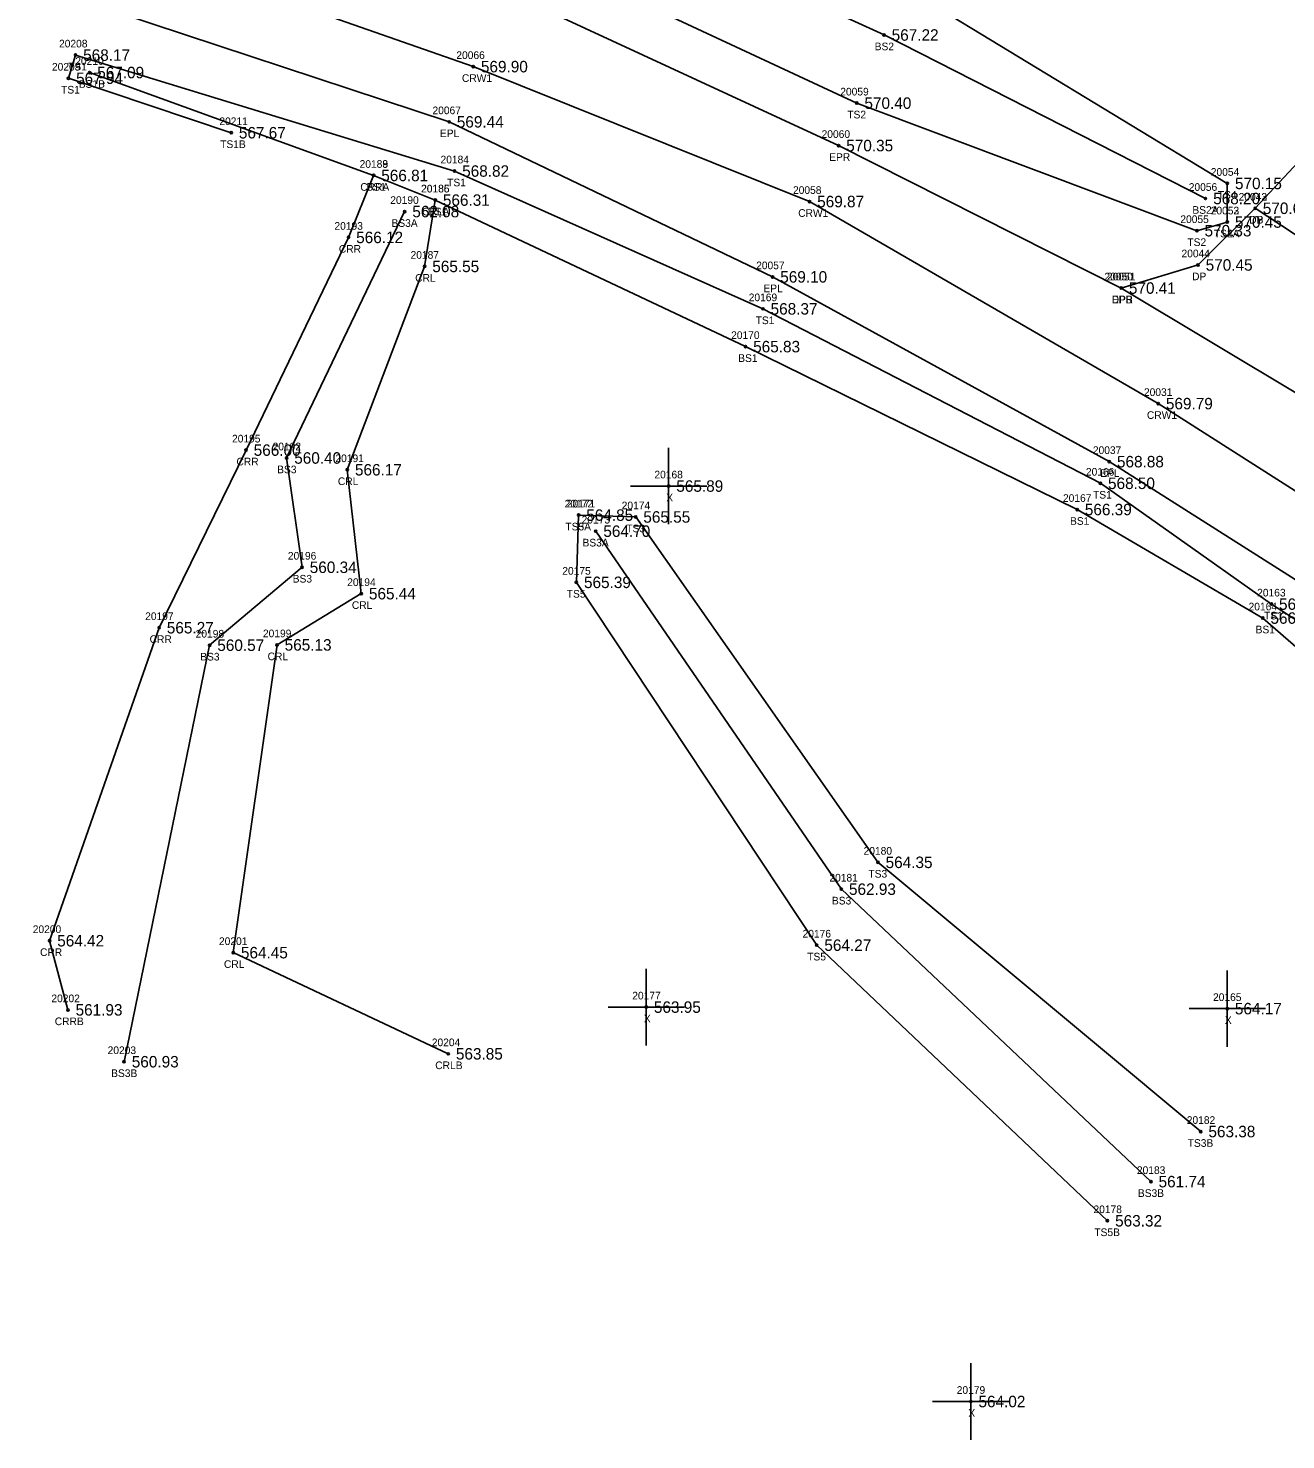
# Model space of a CAD drawing. Extents: x 1530159 to 1531652, y 877045 to 877724.
# Drawn here: x 1531368.6 to 1531533, y 877049.7 to 877234.2 of the extents above; entities that cross this region are included whole.
import ezdxf

# ---------------------------------------------------------------- set-up
doc = ezdxf.new("R2010")
doc.units = 0
for name, color, linetype in [('RD_DTM_BkLn1', 7, 'Continuous'), ('RD_DTM_BkLn2', 7, 'Continuous'), ('RD_DTM_BkLn_txCode', 7, 'Continuous'), ('RD_EX_Driveway', 7, 'Continuous'), ('RD_EX_Driveway_txCode', 7, 'Continuous'), ('RD_EX_H2O', 7, 'Continuous'), ('RD_EX_H2O_txCode', 7, 'Continuous'), ('RD_EX_Misc', 7, 'Continuous'), ('RD_EX_Misc_txCode', 7, 'Continuous'), ('RD_EX_Road', 7, 'Continuous'), ('RD_EX_Road_txCode', 7, 'Continuous'), ('RD_EX_TX_Driveway_ELEV', 7, 'Continuous'), ('RD_EX_TX_H2O_ELEV', 7, 'Continuous'), ('RD_EX_TX_Misc_ELEV', 7, 'Continuous'), ('RD_EX_TX_Road_ELEV', 7, 'Continuous'), ('RD_HC_Survey_ELEV', 7, 'Continuous'), ('RD_HC_Survey_txCode', 7, 'Continuous'), ('RD_SMD_Locator', 7, 'Continuous')]:
    doc.layers.add(name, color=color, linetype=linetype)

msp = doc.modelspace()

# ---------------------------------------------------------------- linework, layer by layer
at = {"layer": 'RD_DTM_BkLn1'}
msp.add_lwpolyline([(1531601.44, 877127.51), (1531558.79, 877158.11), (1531516.37, 877185.16), (1531470.77, 877211.58), (1531426.8, 877229.22), (1531379.86, 877245.66), (1531330.99, 877260.09), (1531284.24, 877270.97), (1531236.44, 877276.73), (1531185.96, 877281.19), (1531132.29, 877281.48), (1531081.11, 877280.78), (1531028.25, 877278.4), (1530978.85, 877276.13), (1530941.18, 877274.78)], dxfattribs=at)
at = {"layer": 'RD_DTM_BkLn2'}
for points in [[(1531525.39, 877208.9), (1531521.42, 877207.77), (1531476.95, 877224.45), (1531434.54, 877244.21), (1531428.71, 877250.7), (1531428.74, 877257.42), (1531435.09, 877260.65), (1531443.68, 877258)], [(1531525.39, 877208.9), (1531525.4, 877213.95), (1531484.44, 877238.83), (1531443.68, 877258)], [(1531522.55, 877211.98), (1531480.51, 877233.36), (1531446.11, 877249.05), (1531438.91, 877251.49), (1531432.85, 877253.78)], [(1531591.14, 877115.14), (1531551.46, 877145.84), (1531531.16, 877158.94), (1531508.8, 877174.74), (1531464.68, 877197.55), (1531424.35, 877215.57), (1531374.79, 877230.73), (1531373.87, 877227.7), (1531395.15, 877220.58)], [(1531586.69, 877110.02), (1531548.92, 877140.72), (1531530.04, 877157.12), (1531505.77, 877171.31), (1531462.4, 877192.61), (1531421.83, 877211.77), (1531413.77, 877214.99), (1531376.63, 877228.45)], [(1531417.83, 877210.27), (1531402.39, 877178.05), (1531404.42, 877163.76), (1531392.33, 877153.57), (1531381.15, 877099.11)], [(1531440.58, 877170.58), (1531440.28, 877161.79), (1531471.71, 877114.35), (1531509.73, 877078.31)], [(1531440.58, 877170.58), (1531448.04, 877170.34), (1531479.72, 877125.18), (1531521.93, 877089.98)], [(1531442.81, 877168.48), (1531474.93, 877121.67), (1531515.41, 877083.43)]]:
    msp.add_lwpolyline(points, dxfattribs=at)
at = {"layer": 'RD_EX_Driveway'}
msp.add_line((1531546.65, 877229.63), (1531529.04, 877210.7), dxfattribs=at)
msp.add_lwpolyline([(1531535.22, 877186.03), (1531535.28, 877194.38), (1531539.23, 877204), (1531529.04, 877210.7), (1531521.57, 877203.29), (1531511.53, 877200.27)], dxfattribs=at)
at = {"layer": 'RD_EX_H2O'}
for points in [[(1531413.77, 877214.99), (1531410.49, 877206.89), (1531397.09, 877179.08), (1531385.73, 877155.86), (1531371.4, 877114.93), (1531373.8, 877105.89)], [(1531421.83, 877211.77), (1531420.44, 877203.1), (1531410.33, 877176.51), (1531412.16, 877160.31), (1531401.14, 877153.61), (1531395.42, 877113.37), (1531423.53, 877100.14)]]:
    msp.add_lwpolyline(points, dxfattribs=at)
at = {"layer": 'RD_EX_Misc'}
for p, q in [((1531452.35, 877169.38), (1531452.35, 877179.38)), ((1531447.35, 877174.38), (1531457.35, 877174.38)), ((1531449.42, 877101.25), (1531449.42, 877111.25)), ((1531525.39, 877101.05), (1531525.39, 877111.05)), ((1531444.42, 877106.25), (1531454.42, 877106.25)), ((1531520.39, 877106.05), (1531530.39, 877106.05)), ((1531491.86, 877049.68), (1531491.86, 877059.68)), ((1531486.86, 877054.68), (1531496.86, 877054.68))]:
    msp.add_line(p, q, dxfattribs=at)
at = {"layer": 'RD_EX_Road'}
for points in [[(1531606.64, 877133.84), (1531579.15, 877155.05), (1531564.87, 877165.27), (1531535.22, 877186.03), (1531511.53, 877200.27), (1531474.57, 877218.9), (1531430.45, 877239.35), (1531404.48, 877249.38), (1531382.32, 877256.43), (1531333.23, 877270.71), (1531303.67, 877277.44), (1531276.52, 877282.71), (1531237.32, 877287.2), (1531185.8, 877290.94), (1531132.61, 877292.77), (1531081.11, 877292.38), (1531038.69, 877288.67), (1530976.42, 877285.45), (1530941.06, 877284.26)], [(1531595.27, 877120.27), (1531553.56, 877149.9), (1531509.97, 877177.57), (1531465.94, 877201.73), (1531423.65, 877222), (1531376.09, 877237.68), (1531328.84, 877252.31), (1531282.81, 877261.85), (1531235.7, 877268.49), (1531185.47, 877272.84), (1531132.72, 877273.12), (1531080.2, 877271.87), (1531029.21, 877269.53), (1530978.47, 877268.32), (1530945.95, 877265.93), (1530941.45, 877262.44)]]:
    msp.add_lwpolyline(points, dxfattribs=at)
at = {"layer": 'RD_SMD_Locator'}
for centre in [(1531480.51, 877233.36), (1531374.79, 877230.73), (1531376.63, 877228.45), (1531426.8, 877229.22), (1531373.87, 877227.7), (1531476.95, 877224.45), (1531395.15, 877220.58), (1531423.65, 877222), (1531474.57, 877218.9), (1531424.35, 877215.57), (1531413.77, 877214.99), (1531413.77, 877214.99), (1531525.4, 877213.95), (1531421.83, 877211.77), (1531421.83, 877211.77), (1531470.77, 877211.58), (1531522.55, 877211.98), (1531417.83, 877210.27), (1531529.04, 877210.7), (1531529.04, 877210.7), (1531521.42, 877207.77), (1531525.39, 877208.9), (1531525.39, 877208.9), (1531410.49, 877206.89), (1531420.44, 877203.1), (1531521.57, 877203.29), (1531465.94, 877201.73), (1531511.53, 877200.27), (1531511.53, 877200.27), (1531464.68, 877197.55), (1531462.4, 877192.61), (1531516.37, 877185.16), (1531397.09, 877179.08), (1531402.39, 877178.05), (1531410.33, 877176.51), (1531509.97, 877177.57), (1531508.8, 877174.74), (1531452.35, 877174.38), (1531505.77, 877171.31), (1531440.58, 877170.58), (1531440.58, 877170.58), (1531448.04, 877170.34), (1531442.81, 877168.48), (1531404.42, 877163.76), (1531440.28, 877161.79), (1531412.16, 877160.31), (1531531.16, 877158.94), (1531530.04, 877157.12), (1531385.73, 877155.86), (1531392.33, 877153.57), (1531401.14, 877153.61), (1531479.72, 877125.18), (1531474.93, 877121.67), (1531371.4, 877114.93), (1531471.71, 877114.35), (1531395.42, 877113.37), (1531449.42, 877106.25), (1531373.8, 877105.89), (1531525.39, 877106.05), (1531381.15, 877099.11), (1531423.53, 877100.14), (1531521.93, 877089.98), (1531515.41, 877083.43), (1531509.73, 877078.31), (1531491.86, 877054.68)]:
    msp.add_circle(centre, 0.15, dxfattribs=at)

# ---------------------------------------------------------------- texts
at = {"layer": 'RD_DTM_BkLn_txCode'}
for s, p in [('20208', (1531372.64, 877231.73)), ('BS2', (1531479.29, 877231.36)), ('20210', (1531374.76, 877229.45)), ('20209', (1531371.71, 877228.7)), ('TS1', (1531373.83, 877228.73)), ('TS1', (1531372.91, 877225.7)), ('BS1B', (1531375.21, 877226.45)), ('20059', (1531474.79, 877225.45)), ('20211', (1531393.6, 877221.58)), ('TS2', (1531475.71, 877222.45)), ('TS1B', (1531393.71, 877218.58)), ('20188', (1531411.94, 877215.99)), ('20184', (1531422.52, 877216.57)), ('20054', (1531523.24, 877214.95)), ('BS1', (1531412.83, 877212.99)), ('20185', (1531419.99, 877212.77)), ('TS1', (1531423.39, 877213.57)), ('20056', (1531520.36, 877212.98)), ('20190', (1531415.95, 877211.27)), ('TS4', (1531524.16, 877211.95)), ('BS1', (1531420.88, 877209.77)), ('20055', (1531519.26, 877208.77)), ('BS2A', (1531520.83, 877209.98)), ('20052', (1531523.23, 877209.9)), ('20053', (1531523.23, 877209.9)), ('BS3A', (1531416.11, 877208.27)), ('TS2A', (1531523.65, 877206.9)), ('TS4A', (1531523.65, 877206.9)), ('TS2', (1531520.18, 877205.77)), ('20169', (1531462.82, 877198.55)), ('TS1', (1531463.72, 877195.55)), ('20170', (1531460.52, 877193.61)), ('BS1', (1531461.45, 877190.61)), ('20192', (1531400.56, 877179.05)), ('BS3', (1531401.16, 877176.05)), ('20166', (1531506.91, 877175.74)), ('20167', (1531503.91, 877172.31)), ('TS1', (1531507.84, 877172.74)), ('20172', (1531438.75, 877171.58)), ('20171', (1531439.03, 877171.58)), ('20174', (1531446.21, 877171.34)), ('TS3A', (1531438.85, 877168.58)), ('TS5A', (1531438.85, 877168.58)), ('20173', (1531440.97, 877169.48)), ('TS3', (1531446.8, 877168.34)), ('BS1', (1531504.83, 877169.31)), ('BS3A', (1531441.09, 877166.48)), ('20196', (1531402.56, 877164.76)), ('20175', (1531438.44, 877162.79)), ('BS3', (1531403.19, 877161.76)), ('TS5', (1531439.03, 877159.79)), ('20163', (1531529.3, 877159.94)), ('20164', (1531528.18, 877158.12)), ('TS1', (1531530.2, 877156.94)), ('BS1', (1531529.1, 877155.12)), ('20198', (1531390.5, 877154.57)), ('BS3', (1531391.1, 877151.57)), ('20180', (1531477.84, 877126.18)), ('20181', (1531473.37, 877122.67)), ('TS3', (1531478.47, 877123.18)), ('BS3', (1531473.7, 877119.67)), ('20176', (1531469.86, 877115.35)), ('TS5', (1531470.47, 877112.35)), ('20203', (1531378.99, 877100.11)), ('BS3B', (1531379.45, 877097.11)), ('20182', (1531520.1, 877090.98)), ('TS3B', (1531520.22, 877087.98)), ('20183', (1531513.58, 877084.43)), ('BS3B', (1531513.71, 877081.43)), ('20178', (1531507.9, 877079.31)), ('TS5B', (1531508.01, 877076.31))]:
    msp.add_text(s, height=1, dxfattribs=at).set_placement(p)
at = {"layer": 'RD_EX_Driveway_txCode'}
for s, p in [('20042', (1531526.88, 877211.7)), ('20043', (1531526.88, 877211.7)), ('DB', (1531528.26, 877208.7)), ('DP', (1531528.26, 877208.7)), ('20044', (1531519.41, 877204.29)), ('20050', (1531509.33, 877201.27)), ('DP', (1531520.79, 877201.29)), ('DPB', (1531510.28, 877198.27))]:
    msp.add_text(s, height=1, dxfattribs=at).set_placement(p)
at = {"layer": 'RD_EX_H2O_txCode'}
for s, p in [('20189', (1531411.94, 877215.99)), ('CRRA', (1531412.03, 877212.99)), ('20186', (1531419.97, 877212.77)), ('CRLA', (1531420.11, 877209.77)), ('20193', (1531408.65, 877207.89)), ('CRR', (1531409.23, 877204.89)), ('20187', (1531418.6, 877204.1)), ('CRL', (1531419.21, 877201.1)), ('20195', (1531395.26, 877180.08)), ('20191', (1531408.78, 877177.51)), ('CRR', (1531395.84, 877177.08)), ('CRL', (1531409.1, 877174.51)), ('20194', (1531410.32, 877161.31)), ('CRL', (1531410.93, 877158.31)), ('20197', (1531383.9, 877156.86)), ('CRR', (1531384.48, 877153.86)), ('20199', (1531399.3, 877154.61)), ('CRL', (1531399.91, 877151.61)), ('20200', (1531369.2, 877115.93)), ('CRR', (1531370.15, 877112.93)), ('20201', (1531393.55, 877114.37)), ('CRL', (1531394.2, 877111.37)), ('20202', (1531371.64, 877106.89)), ('CRRB', (1531372.08, 877103.89)), ('20204', (1531421.38, 877101.14)), ('CRLB', (1531421.83, 877098.14))]:
    msp.add_text(s, height=1, dxfattribs=at).set_placement(p)
at = {"layer": 'RD_EX_Misc_txCode'}
for s, p in [('20168', (1531450.49, 877175.38)), ('X', (1531452.04, 877172.38)), ('20177', (1531447.59, 877107.25)), ('20165', (1531523.53, 877107.05)), ('X', (1531449.11, 877104.25)), ('X', (1531525.08, 877104.05)), ('20179', (1531490.02, 877055.68)), ('X', (1531491.54, 877052.68))]:
    msp.add_text(s, height=1, dxfattribs=at).set_placement(p)
at = {"layer": 'RD_EX_Road_txCode'}
for s, p in [('20067', (1531421.47, 877223)), ('EPL', (1531422.44, 877220)), ('20060', (1531472.35, 877219.9)), ('EPR', (1531473.34, 877216.9)), ('20057', (1531463.79, 877202.73)), ('20051', (1531509.66, 877201.27)), ('EPL', (1531464.74, 877199.73)), ('EPR', (1531510.3, 877198.27)), ('20037', (1531507.82, 877178.57)), ('EPL', (1531508.77, 877175.57))]:
    msp.add_text(s, height=1, dxfattribs=at).set_placement(p)
at = {"layer": 'RD_EX_TX_Driveway_ELEV'}
for s, p in [('570.62', (1531530.04, 877209.95)), ('570.62', (1531530.04, 877209.95)), ('570.45', (1531522.57, 877202.54)), ('570.41', (1531512.53, 877199.52))]:
    msp.add_text(s, height=1.5, dxfattribs=at).set_placement(p)
at = {"layer": 'RD_EX_TX_H2O_ELEV'}
for s, p in [('566.81', (1531414.77, 877214.24)), ('566.31', (1531422.83, 877211.02)), ('566.12', (1531411.49, 877206.14)), ('565.55', (1531421.44, 877202.35)), ('566.00', (1531398.09, 877178.33)), ('566.17', (1531411.33, 877175.76)), ('565.44', (1531413.16, 877159.56)), ('565.27', (1531386.73, 877155.11)), ('565.13', (1531402.14, 877152.86)), ('564.42', (1531372.4, 877114.18)), ('564.45', (1531396.42, 877112.62)), ('561.93', (1531374.8, 877105.14)), ('563.85', (1531424.53, 877099.39))]:
    msp.add_text(s, height=1.5, dxfattribs=at).set_placement(p)
at = {"layer": 'RD_EX_TX_Misc_ELEV'}
for s, p in [('567.22', (1531481.51, 877232.61)), ('568.17', (1531375.79, 877229.98)), ('567.94', (1531374.87, 877226.95)), ('567.09', (1531377.63, 877227.7)), ('570.40', (1531477.95, 877223.7)), ('567.67', (1531396.15, 877219.83)), ('566.81', (1531414.77, 877214.24)), ('568.82', (1531425.35, 877214.82)), ('570.15', (1531526.4, 877213.2)), ('566.31', (1531422.83, 877211.02)), ('568.20', (1531523.55, 877211.23)), ('562.08', (1531418.83, 877209.52)), ('570.45', (1531526.39, 877208.15)), ('570.45', (1531526.39, 877208.15)), ('570.33', (1531522.42, 877207.02)), ('568.37', (1531465.68, 877196.8)), ('565.83', (1531463.4, 877191.86)), ('560.40', (1531403.39, 877177.3)), ('565.89', (1531453.35, 877173.63)), ('568.50', (1531509.8, 877173.99)), ('564.85', (1531441.58, 877169.83)), ('564.85', (1531441.58, 877169.83)), ('565.55', (1531449.04, 877169.59)), ('566.39', (1531506.77, 877170.56)), ('564.70', (1531443.81, 877167.73)), ('560.34', (1531405.42, 877163.01)), ('565.39', (1531441.28, 877161.04)), ('568.18', (1531532.16, 877158.19)), ('566.85', (1531531.04, 877156.37)), ('560.57', (1531393.33, 877152.82)), ('564.35', (1531480.72, 877124.43)), ('562.93', (1531475.93, 877120.92)), ('564.27', (1531472.71, 877113.6)), ('563.95', (1531450.42, 877105.5)), ('564.17', (1531526.39, 877105.3)), ('560.93', (1531382.15, 877098.36)), ('563.38', (1531522.93, 877089.23)), ('561.74', (1531516.41, 877082.68)), ('563.32', (1531510.73, 877077.56)), ('564.02', (1531492.86, 877053.93))]:
    msp.add_text(s, height=1.5, dxfattribs=at).set_placement(p)
at = {"layer": 'RD_EX_TX_Road_ELEV'}
for s, p in [('569.44', (1531424.65, 877221.25)), ('570.35', (1531475.57, 877218.15)), ('569.10', (1531466.94, 877200.98)), ('570.41', (1531512.53, 877199.52)), ('568.88', (1531510.97, 877176.82))]:
    msp.add_text(s, height=1.5, dxfattribs=at).set_placement(p)
at = {"layer": 'RD_HC_Survey_ELEV'}
for s, p in [('569.90', (1531427.8, 877228.47)), ('569.87', (1531471.77, 877210.83)), ('569.79', (1531517.37, 877184.41))]:
    msp.add_text(s, height=1.5, dxfattribs=at).set_placement(p)
at = {"layer": 'RD_HC_Survey_txCode'}
for s, p in [('20066', (1531424.59, 877230.22)), ('CRW1', (1531425.32, 877227.22)), ('20058', (1531468.61, 877212.58)), ('CRW1', (1531469.29, 877209.58)), ('20031', (1531514.5, 877186.16)), ('CRW1', (1531514.89, 877183.16))]:
    msp.add_text(s, height=1, dxfattribs=at).set_placement(p)

doc.saveas('drawing.dxf')
